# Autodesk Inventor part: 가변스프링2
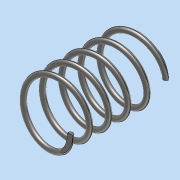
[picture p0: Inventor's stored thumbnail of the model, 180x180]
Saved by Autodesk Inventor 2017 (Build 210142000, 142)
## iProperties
Part Number: 가변스프링2
Material: 강철, 연강
Document SubType Name: Modeling
Designer: MRC
Density: 7.85 g/cm^3
Appearance: 반연마
Mass: 8.42454 g
Surface Area: 21.7273 cm^2
Volume: 1.07319 cm^3
Author: MRC
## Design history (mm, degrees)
sketch "스케치1"
  geometry: L1 (0, 0)-(0, 37.411); L2 (0, 0)-(11, 0); L3 (0, 37.411)-(11, 37.411); C1 r 1 at (11, 0)
  constraints: 6 end point, 2 horizontal, 1 centre point, 1 coincident, 1 vertical
  dimensions: "d0" = 37.4112 distance of L1.start L1.end (derived); "d1" = 11 distance of L1.end L3.end; "d2" = 11 distance of L1.start L2.end; "d3" = 2 diameter of C1
feature "코일1" sketch "스케치1" pitch "d4" = 10; turns "d6" = 5; dims "d5" = 37.4112 (= d0), "d7" = 0, angle "d8" = 90 deg, angle "d9" = 90 deg, "d10" = 0, "d11" = 0
sketch "스케치2"
  geometry: L1 (37.411, 15)-(0, 15); L2 (0, 15)-(0, -15); L3 (0, -15)-(37.411, -15); L4 (37.411, -15)-(37.411, 15); 2 further points
  constraints: 8 end point, 2 parallel, 1 coincident, 1 horizontal, 1 midpoint, 1 perpendicular
  dimensions: "d12" = 37.4112 distance of L2.end L3.end (= d0); "d13" = 30 distance of L3.end L1.start
extrude "돌출1" sketch "스케치2" stored distance "d14" = 0; taper "d15" = 0 deg
node "솔리드1"
